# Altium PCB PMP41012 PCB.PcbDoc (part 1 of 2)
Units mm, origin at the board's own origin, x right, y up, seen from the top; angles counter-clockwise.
Board outline 69 x 32 mm, 2 copper layers (Top Layer, Bottom Layer), stack 1.575 mm thick; 63 components, 34 nets, 139 pads, 27 vias.
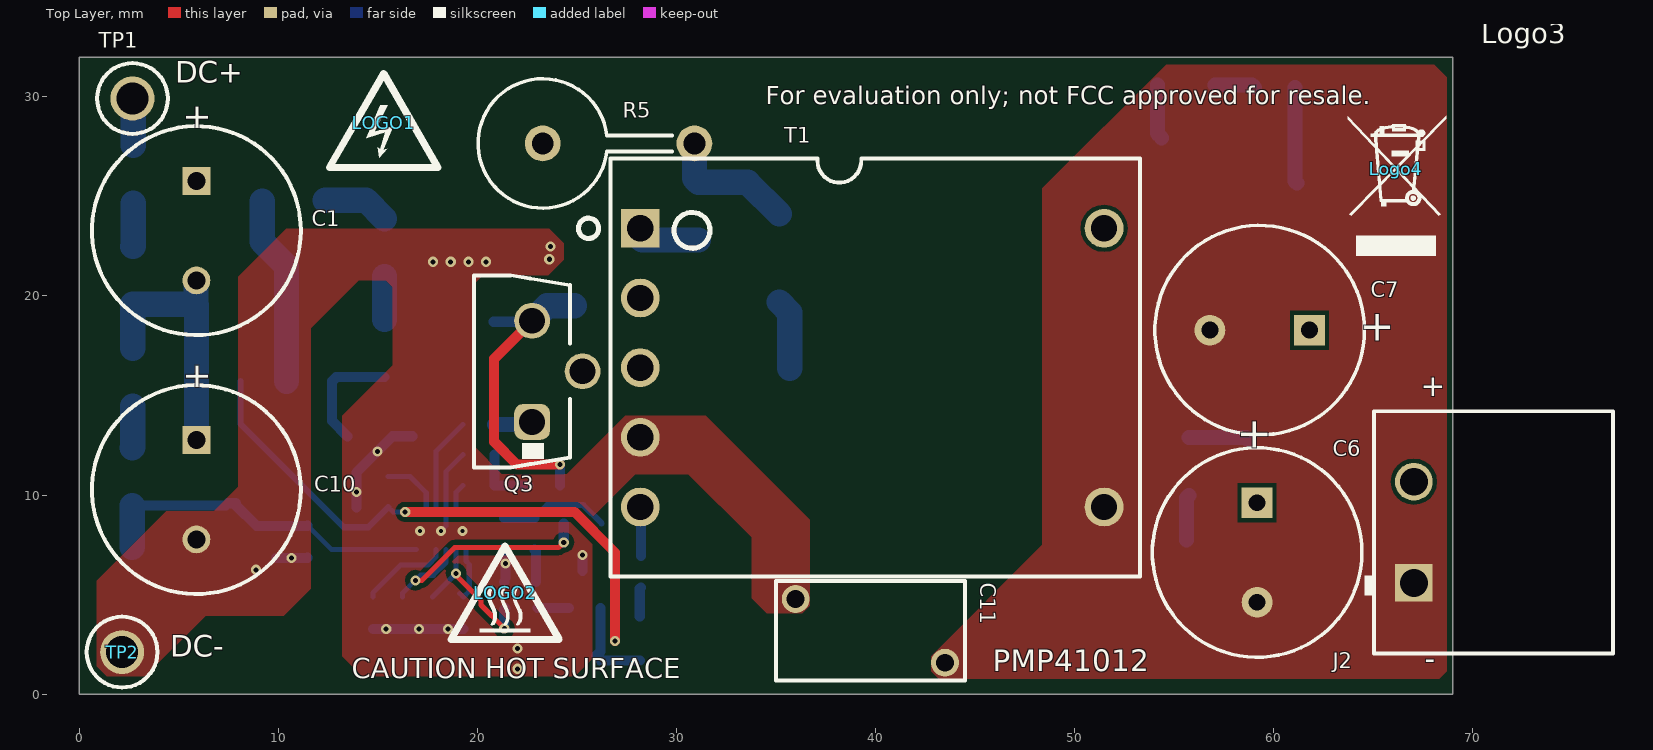
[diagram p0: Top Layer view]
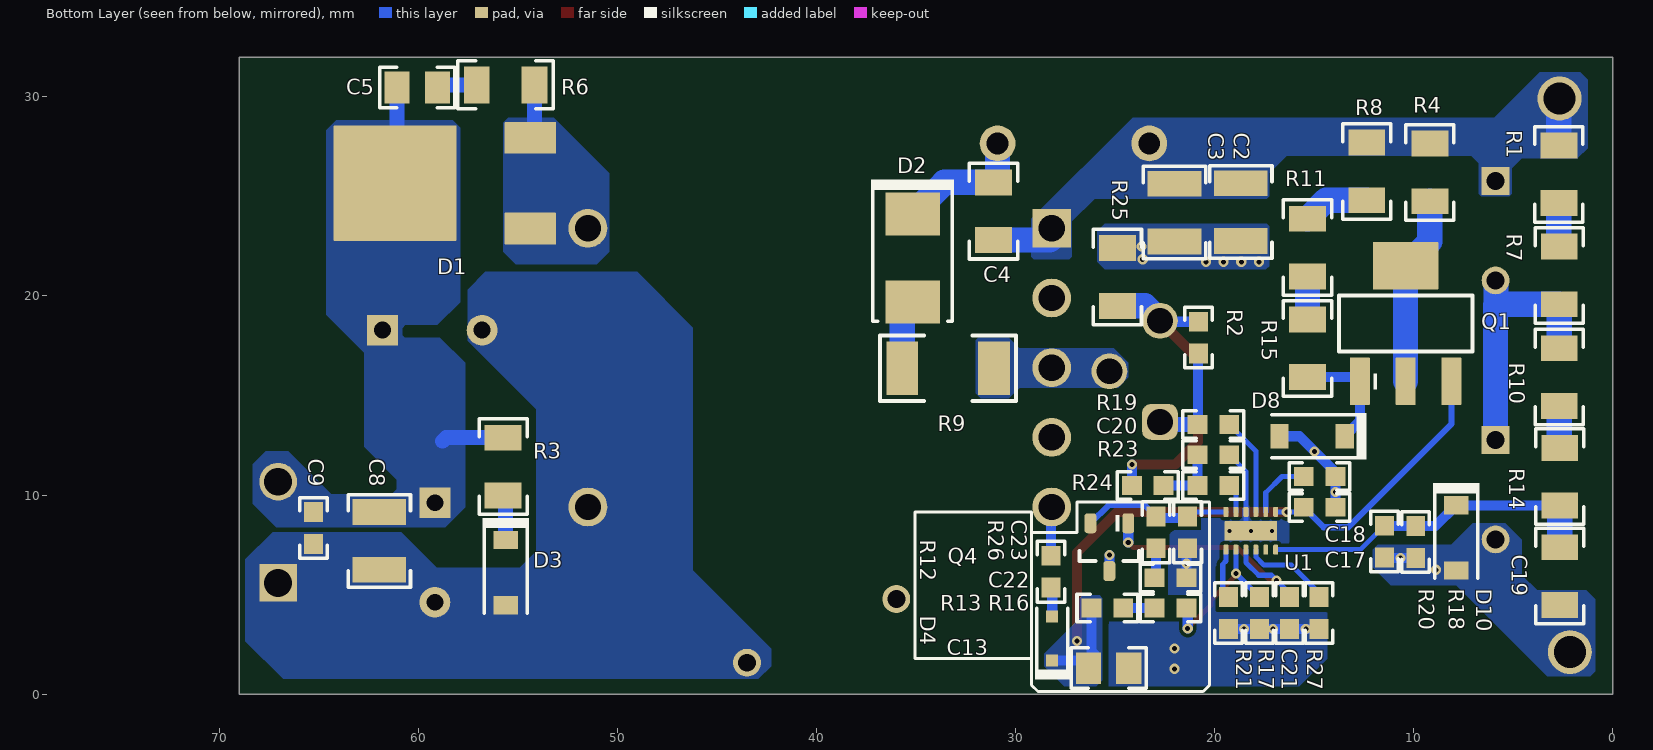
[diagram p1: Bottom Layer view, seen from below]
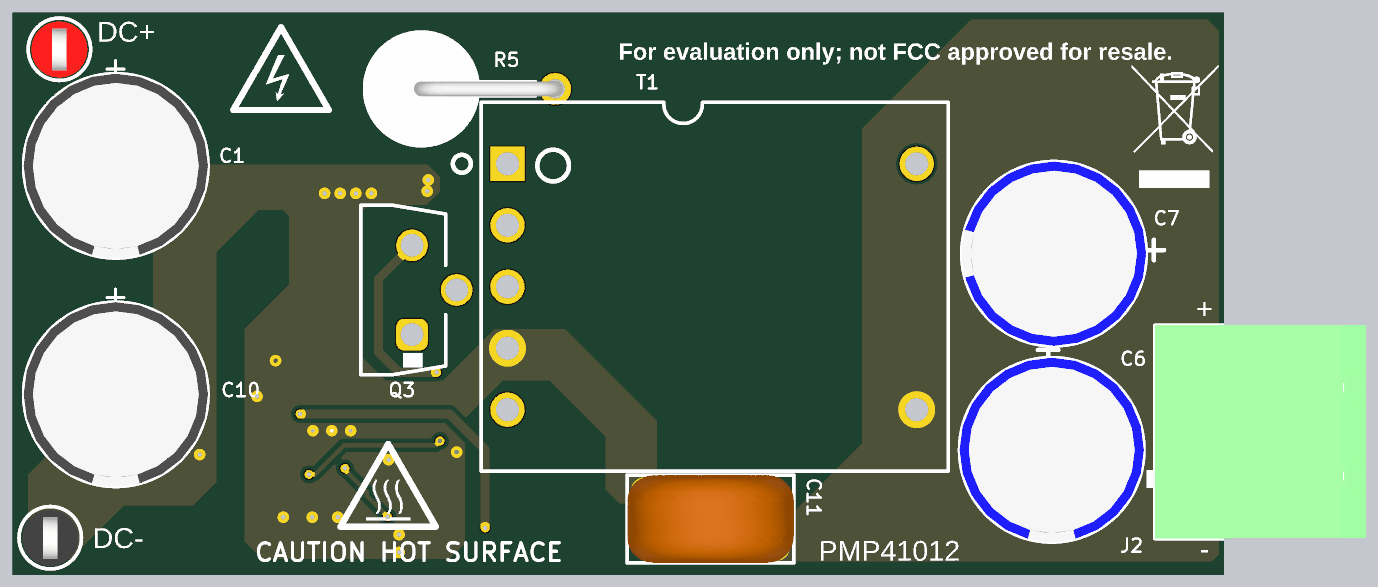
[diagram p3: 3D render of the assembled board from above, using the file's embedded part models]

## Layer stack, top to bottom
Top Solder: solder mask 0.0102, Solder Resist, Dk 3.5
Top Layer: signal copper 0.0356
Dielectric1: core 1.5037, FR-4, Dk 4.8
Bottom Layer: signal copper 0.0356
Bottom Solder: solder mask 0.0102, Solder Resist, Dk 3.5

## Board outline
0,0 69,0 69,32 0,32

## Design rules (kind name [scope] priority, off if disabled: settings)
AcuteAngle [All] p1: minimum=4.50000000000000E+0001 checktracksonly=FALSE
AssemblyTestPointUsage [All] p1: valid=2
Clearance Clearance_BoardEdge_MountingHoles [OnCopper and InComponentClass('Mounting Holes') vs IsKeepOut] p1: gap=1.016 ignorepadtopadclearanceinfootprint=FALSE except(0: Arc-Hole Track-Hole SMDPad-Hole THPad-Hole Via-Hole Fill-Hole Poly-Hole Region-Hole Text-Hole)
Clearance Clearance_BoardEdge_Poly [OnCopper and InPoly vs IsKeepOut] p2: gap=0.635 ignorepadtopadclearanceinfootprint=FALSE except(0: Arc-Hole Track-Hole SMDPad-Hole THPad-Hole Via-Hole Fill-Hole Poly-Hole Region-Hole Text-Hole)
Clearance Clearance_BoardEdge [OnCopper and Not InComponentClass('Logo') and not InComponentClass('FiducialMark') and not InRegion(1000,500,4000,800) and Not IsKeepout vs IsKeepOut] p3: gap=0.127 ignorepadtopadclearanceinfootprint=FALSE except(0: Arc-Hole Track-Hole SMDPad-Hole THPad-Hole Via-Hole Fill-Hole Poly-Hole Region-Hole Text-Hole)
Clearance Clearance_Poly [InPolygon] p4: gap=0.198 ignorepadtopadclearanceinfootprint=FALSE
Clearance [All] p5: gap=0.198 ignorepadtopadclearanceinfootprint=FALSE
ComponentClearance ComponentClearance_Logo [All] p1: gap=0.254 collisioncheckmode=3 verticalgap=0.254 showdistances=TRUE
ComponentClearance ComponentClearance_ScrewToNut [(HasFootprint('NY PMS 440 0025 PH')) vs (HasFootprint('Keystone_1902C'))] p2: gap=0.127 collisioncheckmode=3 verticalgap=0.254 showdistances=FALSE
ComponentClearance ComponentClearance_MountingHoles [InComponentClass('Mounting Holes')] p3: gap=0.254 collisioncheckmode=3 verticalgap=2540 showdistances=FALSE
ComponentClearance ComponentClearance_SmallPassives [HasFootprint('0201*') or HasFootprint('0402*') or HasFootprint('0508') or HasFootprint('0603*') or HasFootprint('0612') or HasFootprint('0805*') or HasFootprint('0815*') or HasFootprint('0830*') or HasFootprint('1206*') or HasFootprint('1210*') or HasFootprint('1808*') or HasFootprint('1812*') or HasFootprint('1825*') or HasFootprint('2010*') or HasFootprint('2220*') or HasFootprint('2225*') or HasFootprint('2512*') or HasFootprint('2728*') or HasFootprint('3518*') vs HasFootprint('0201*') or HasFootprint('0402*') or HasFootprint('0508') or HasFootprint('0603*') or HasFootprint('0612') or HasFootprint('0805*') or HasFootprint('0815*') or HasFootprint('0830*') or HasFootprint('1206*') or HasFootprint('1210*') or HasFootprint('1808*') or HasFootprint('1812*') or HasFootprint('1825*') or HasFootprint('2010*') or HasFootprint('2220*') or HasFootprint('2225*') or HasFootprint('2512*') or HasFootprint('2728*') or HasFootprint('3518*')] p4: gap=0.254 collisioncheckmode=3 verticalgap=0.254 showdistances=FALSE
ComponentClearance ComponentClearance_THtoSMT [IsThruComponent vs IsSMTComponent] p5: gap=0.254 collisioncheckmode=3 verticalgap=2540 showdistances=FALSE
ComponentClearance ComponentClearance_THtoTH [IsThruComponent vs IsThruComponent] p6: gap=0.254 collisioncheckmode=3 verticalgap=2540 showdistances=FALSE
ComponentClearance [All] p7: gap=0.254 collisioncheckmode=3 verticalgap=0.254 showdistances=FALSE
DiffPairsRouting [All] p1: maxlimit=2.54 minlimit=0.254 mostfreqgap=0.254 toplayer_minwidth=0.381 toplayer_maxwidth=0.381 toplayer_prefwidth=0.381 bottomlayer_minwidth=0.381 bottomlayer_maxwidth=0.381 bottomlayer_prefwidth=0.381 maxuncoupledlength=25.4
FabricationTestPointUsage TestPointUsage [All] p1: valid=2 allowmultiple=FALSE
FabricationTestpoint Testpoint [All] p1: side=3 testpointundercomponent=TRUE minsize=1.016 maxsize=2.54 preferedsize=1.524 minholesize=0 maxholesize=1.016 preferedholesize=0.813 testpointgrid=0.025 allowsidetop=TRUE allowsidebottom=TRUE usegrid=TRUE gridtolerance=0
FanoutControl Fanout_LCC [IsLCC] p1: bgadir=Out bgaviamode=Centered fanoutstyle=Auto fanoutdirection=Alternating viagrid=0.025 // Fanout_LCC (Default Rule)
FanoutControl Fanout_BGA [IsBGA] p2: bgadir=Out bgaviamode=Centered fanoutstyle=Auto fanoutdirection=Alternating viagrid=0.025 // Fanout_BGA (Default Rule)
FanoutControl Fanout_Default [All] p4: bgadir=Out bgaviamode=Centered fanoutstyle=Auto fanoutdirection=Alternating viagrid=0.025 // Fanout_Default (Default Rule)
FanoutControl Fanout_Small [(CompPinCount < 5)] p5: bgadir=Out bgaviamode=Centered fanoutstyle=Auto fanoutdirection=OutThenIn viagrid=0.025 // Fanout_Small (Default Rule)
HoleSize [All] p1: absolutevalues=TRUE maxlimit=6.375 minlimit=0.152 maxpercent=80.000 minpercent=20.000
MinimumAnnularRing [All] p1: minimumring=0.076
MinimumSolderMaskSliver MinimumSolderMaskSliver_Logo [InComponentClass('Logo') vs InComponentClass('Logo')] p1: minsoldermaskwidth=0.018
MinimumSolderMaskSliver [All] p2: minsoldermaskwidth=0
PlaneConnect [All] p1: planeconnectstyle=Direct reliefexpansion=0.254 reliefentries=4 reliefconductorwidth=0.254 reliefairgap=0.254
PolygonConnect [All] p1: connectstyle=Direct reliefconductorwidth=0.254 reliefentries=4 polygonreliefangle="90 Angle" airgapwidth=0.254
RoutingCorners [All] p1: cornerstyle=45-Degree minsetback=0.254 maxsetback=2.54
RoutingVias [All] p1: holewidth=0.406 width=0.864 viastyle="Through Hole" minholewidth=0.203 minwidth=0.406 maxholewidth=1.016 maxwidth=1.651
SMDToCorner [All] p1: distance=0
SilkToBoardRegionClearance [Not ((IsComment or IsDesignator) And (Hide <> 'False')) and not InRegion(1000,500,4000,800)] p1:
SilkToSilkClearance [All] p1: silktosilkclearance=0
SilkToSolderMaskClearance SilkscreenOverComponentPads [IsPad] p1: minsilkscreentomaskgap=0 clearancetoexposedcopper=TRUE
SolderMaskExpansion [All] p1: expansion=0.076
Width [All] p1: maxlimit=2.54 minlimit=0.152 preferedwidth=0.254 checkconnectedcopper=TRUE
14 further rules are at their usual default settings.

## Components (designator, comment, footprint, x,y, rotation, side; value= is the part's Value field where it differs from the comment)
C1 "B43851A9106M" B43851_1000x2000 5.893,23.281 r270 top value=10uF
C2 "GRM32DR73A223KW01L" 1210_220 18.694,24.216 r270 bottom value=0.022uF
C3 "GRM32DR73A223KW01L" 1210_220 22.021,24.191 r270 bottom value=0.022uF
C4 "C1206C562J2GACAUTO" 1206 31.115,24.257 r90 bottom value=5600pF
C5 "GRM21AR72E102KW01D" 0805_HV 60.071,30.48 r180 bottom value=1000pF
C6 "EEU-FR1E102B" FR_1000x2000 59.182,7.112 r270 top value=1000uF
C7 "EEU-FR1E102B" FR_1000x2000 59.309,18.281 r180 top value=1000uF
C8 "GRM32DR71E106KA12L" 1210_220 61.976,7.694 r270 bottom value=10uF
C9 "GRM188R71H104KA93D" 0603 65.278,8.344 r270 bottom value=0.1uF
C10 "B43851A9106M" B43851_1000x2000 5.893,10.272 r270 top value=10uF
C11 "AY2222M35Y5US63L7" AY2_950x500_Straight 39.751,3.175 r0 top value=2200pF
C13 "CGA4J3X7R1H225K125AB" 0805_HV 25.333,1.3 r180 bottom value=2.2uF
C17 "GRM188R71H104KA93D" 0603 14.732,9.385 r0 bottom value=0.1uF
C18 "GRM188R71E105KA12D" 0603 14.732,10.934 r0 bottom value=1uF
C19 "GRM319R71H334KA01D" 1206 2.667,5.929 r270 bottom value=0.33uF
C20 "GRM188R71H221KA01D" 0603 20.075,12.024 r180 bottom value=220pF
C21 "GRM188R71C474KA88D" 0603 16.256,4.076 r270 bottom value=0.47uF
C22 "GRM188R71A105KA61D" 0603 22.225,5.842 r180 bottom value=1uF
C23 "GRM188R71H102KA01D" 0603 21.361,8.128 r270 bottom value=1000pF
D1 "MBRD20150CT-13" DPAK 57.785,25.666 r0 bottom value=150V
D2 "RS1MB-13-F" SMB 35.179,21.905 r270 bottom value=1000V
D3 "MMSZ5250B-7-F" SOD-123 55.626,6.096 r270 bottom value=20V
D4 "BAV21WS-7-F" SOD-323 28.168,2.794 r90 bottom value=250V
D8 "MMSZ5245B-7-F" SOD-123 15.113,12.954 r0 bottom value=15V
D10 "MMSZ5231B-7-F" SOD-123 7.874,7.852 r270 bottom value=5.1V
J2 "1757242" PHOENIX_1757242 71.056,8.128 r90 top
LOGO1 "DANGER HIGH VOLTAGE" IEC_HighVoltage_Small 15.3,28.7 r0 top
LOGO2 "CAUTION HOT SURFACE" IEC_HotSurface_Small 21.4,5.1 r0 top
Logo3 "FCC disclaimer" FCC_disclaimer 70.923,15.736 r90 top
Logo4 "WEEE logo" WEEE_Minimum 66.159,26.4 r0 top
Q1 "IPN80R3K3P7" SOT-223 10.414,18.615 r90 bottom value=800V
Q3 "STF2N95K5" TO-220_FullPAK_Offset 22.758,16.215 r90 top value=800V
Q4 "MMBT3906" SOT-23 25.298,7.379 r270 bottom value="40 V"
R1 "CRCW1206200KJNEA" 1206 2.713,26.112 r90 bottom value=200k
R2 "RC0603FR-0747KL" 0603 20.828,17.907 r270 bottom value=47.0k
R3 "CRCW1206100RJNEA" 1206 55.753,11.43 r90 bottom value=100
R4 "CRCW120610K0FKEAHP" 1206 9.194,26.21 r90 bottom value=10.0k
R5 "PR03000202203JAC00" ERG3S_VERT 23.291,27.665 r0 top value=220k
R6 "CRCW12061R00JNEA" 1206 55.626,30.607 r0 bottom value=1.0
R7 "CRCW1206200KJNEA" 1206 2.692,21.031 r90 bottom value=200k
R8 "CRCW1206499KFKEA" 1206 12.369,26.261 r90 bottom value=499k
R9 "CRCW201020R0FKEF" 2010 33.401,16.367 r180 bottom value=20.0
R10 "CRCW1206200KJNEA" 1206 2.692,15.926 r90 bottom value=200k
R11 "CRCW1206499KFKEA" 1206 15.342,22.428 r90 bottom value=499k
R12 "CRCW060310R0JNEA" 0603 28.219,6.147 r90 bottom value=10
R13 "CRCW060349R9FKEA" 0603 25.4,4.318 r0 bottom value=49.9
R14 "CRCW1206200KJNEA" 1206 2.667,10.92 r90 bottom value=200k
R15 "CRCW1206499KFKEA" 1206 15.342,17.371 r90 bottom value=499k
R16 "CRCW06032K80FKEA" 0603 22.225,4.318 r0 bottom value=2.80k
R17 "CRCW0603200RFKEA" 0603 17.756,4.076 r90 bottom value=200
R18 "CRCW0603205KFKEA" 0603 9.906,7.645 r90 bottom value=205k
R19 "CRCW060320R0FKEA" 0603 20.075,13.548 r180 bottom value=20.0
R20 "CRCW060320K5FKEA" 0603 11.481,7.658 r90 bottom value=20.5k
R21 "CRCW06030000Z0EA" 0603 19.306,4.076 r90 bottom value=0
R23 "CRCW06030000Z0EA" 0603 20.075,10.475 r0 bottom value=0
R24 "CRCW06031K62FKEA" 0603 23.368,10.475 r180 bottom value=1.62k
R25 "CSR1206FKR100" 1206 24.892,20.955 r270 bottom value=0.1
R26 "CRCW06032K49FKEA" 0603 22.948,8.128 r90 bottom value=2.49k
R27 "CRCW0603221KFKEA" 0603 14.756,4.076 r90 bottom value=221k
T1 "070-7080" PCBComponent_1 28.194,16.398 r0 top
TP1 "5010" Keystone5010 2.681,29.921 r0 top
TP2 "5011" Keystone5011 2.159,2.108 r0 top
U1 "LM51561QDSSRQ1" DSS0012C 18.19,8.203 r270 bottom

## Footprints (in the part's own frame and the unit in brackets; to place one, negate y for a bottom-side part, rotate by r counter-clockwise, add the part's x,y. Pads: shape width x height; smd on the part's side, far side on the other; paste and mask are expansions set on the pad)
0603 [mm] "0603 from SM-752 data"
  rect 1x0.95 smd: 1(-0.8,0) 2(0.8,0)
  silkscreen extent -1.52,-0.69 1.52,0.69, body extent -0.87,-0.47 0.87,0.47, height 1
0805_HV [mil] "0805 with 30mil clearance between pads"
  rect 50x63 smd: 1(-40,0) 2(40,0)
  silkscreen extent -74,-40 74,40, body extent -43,-29 43,29, height 57
1206 [mm] "1206 from SM-752 data"
  rect 1.3x1.85 smd: 1(-1.45,0) 2(1.45,0)
  silkscreen extent -2.4,-1.21 2.4,1.21, body extent -1.7,-0.9 1.7,0.9, height 1.35
1210_220 [mm] "1210"
  rect 1.3x2.7 smd: 1(-1.45,0) 2(1.45,0)
  silkscreen extent -2.32,-1.57 2.32,1.57, body extent -1.7,-1.35 1.7,1.35, height 2.2
2010 [mm] "Chip Capacitor, Body 5.08x2.54mm, IPC Medium Density"
  rect 1.6x2.7 smd: 1(-2.3,0) 2(2.3,0)
  silkscreen extent -3.42,-1.65 3.42,1.65, body extent -2.73,-1.45 2.73,1.45, height 1.66
AY2_950x500_Straight [mm] "TH, 2-Leads, 9.5x5mm, Pin Spacing 7.5mm"
  round 1.4 hole 0.9: 1(-3.75,1.6) 2(3.75,-1.6)
  silkscreen extent -4.75,-2.5 4.75,2.5, body extent -4.74,-2.5 4.75,2.5, height 12.5
B43851_1000x2000 [mm] "TH, 2-Leads, Dia 10mm, Pin Spacing 5mm"
  rect 1.4x1.4 hole 0.9: 1(-2.5,0)
  round 1.4 hole 0.9: 2(2.5,0)
  silkscreen extent -5.25,-5.25 5.25,5.25, body extent -5.21,-5.24 5.24,5.24, height 22.01
DPAK [mm] "D-PAK, 3-Pads, Body 6.22x6.73mm (max), TO-252AA using nominal STEP model"
  rrect6% 2.6x1.6 smd: 1(-3.4,2.28) 3(-3.4,-2.28)
  rrect2% 6.2x5.8 smd paste-3: 2(3.4,0)
  body extent -3.86,-3.29 5.84,3.29, height 2.48
DSS0012C [mm] "WSON-12"
  rrect40% 0.5x0.25 smd: 1(-0.95,1.25) 2(-0.95,0.75) 3(-0.95,0.25) 4(-0.95,-0.25) 5(-0.95,-0.75) 6(-0.95,-1.25) 7(0.95,-1.25) 8(0.95,-0.75) 9(0.95,-0.25) 10(0.95,0.25) 11(0.95,0.75) 12(0.95,1.25)
  rrect11% 0.95x1.17 on Bottom Paste: 13(0,-0.685) 13(0,0.685)
  rrect11% 1x2.65 smd paste-0.5: 13(0,0)
  body extent -1,-1.5 1,1.5, height 0.81
ERG3S_VERT [mm] "PANASONIC"
  round 1.8 hole 1.1: 1(0,0) 2(7.62,0)
  silkscreen extent -3.25,-3.25 6.5,3.25, body extent -3.24,-3.25 8.04,3.22, height 20.47
FCC_disclaimer [mm]
FR_1000x2000 [mm] "PANASONIC"
  rect 1.55x1.55 hole 0.85: 1(-2.5,0)
  round 1.55 hole 0.85: 2(2.5,0)
  silkscreen extent -5.26,-5.26 5.26,5.26, body extent -5.21,-5.24 5.24,5.24, height 22.01
IEC_HighVoltage_Small [mm]
  silkscreen extent -2.72,-2.24 2.72,2.47
IEC_HotSurface_Small [mm]
  silkscreen extent -2.72,-2.36 2.72,2.35
Keystone5010 [mil] "Keystone Multipurpose loops"
  round 87 hole 63: 1(0,0)
  silkscreen extent -70,-70 70,70, body extent -63,-63 63,62, height 319
Keystone5011 [mil] "Keystone Multipurpose loops"
  round 87 hole 63: 1(0,0)
  silkscreen extent -70,-70 70,70, body extent -63,-63 63,62, height 319
PCBComponent_1 [mm] "THT, Body 22.2.0x25.0mm, 14Pins,Pitch 2.49mm"
  rect 1.95x1.95 hole 1.32: 1(0,7)
  round 1.95 hole 1.32: 2(0,3.5) 3(0,0) 4(0,-3.5) 5(0,-7) 6(23.3,-7) 7(23.3,7)
  silkscreen extent -3.11,-10.5 25.1,10.5
PHOENIX_1757242 [mm] "Header, 5.08 mm, 2x1, R/A, TH"
  rect 1.9x1.9 hole 1.4: 1(-2.54,4)
  round 1.9 hole 1.4: 2(2.54,4)
  silkscreen extent -6.08,-6 6.08,6.47, body extent -6.06,-6.02 6.1,5.98, height 8.6
SMB [mm] "Molded Diode, 2-Leads, Body 5.4x3.6mm, IPC Medium Density, based on OnSemi component dimensions"
  rect 2.159x2.743 smd: 1(-2.21,0) 2(2.21,0)
  silkscreen extent -3.94,-2.08 3.18,2.08, body extent -2.7,-1.8 2.7,1.8, height 2.32
SOD-123 [mm] "On Semi recommended land pattern"
  rect 0.915x1.22 smd: 1(-1.637,0) 2(1.637,0)
  silkscreen extent -2.74,-1.17 2.03,1.17, body extent -1.93,-0.9 1.93,0.9, height 1.35
SOD-323 [mm] "NXP recommended land pattern"
  rect 0.6x0.6 smd paste-0.05: 1(-1.1,0) 2(1.1,0)
  silkscreen extent -2.06,-0.86 1.53,0.86, body extent -1.3,-0.67 1.3,0.68, height 1.1
SOT-23 [mm] "SOT23, 3-Leads, Body 2.9x1.3mm, Pitch 0.95mm, Lead Span 2.5mm, IPC Medium Density"
  rrect50% 1x0.6 smd: 1(-1.2,0.95) 2(-1.2,-0.95) 3(1.2,0)
  silkscreen extent -1.63,-1.5 0.7,1.5, body extent -1.16,-1.45 1.21,1.45, height 1
SOT-223 [mm] "SOT223/SC73, 4-Leads, Body 6.5x3.5mm, Pitch 2.3mm, Lead Span 7mm, IPC Medium Density"
  rrect10% 2.4x1 smd: 1(-2.9,2.3) 2(-2.9,0) 3(-2.9,-2.3)
  rrect4% 2.4x3.3 smd: 4(2.9,0)
  silkscreen extent -3.32,-3.35 1.4,3.35, body extent -3.5,-3.25 3.5,3.25, height 1.62
TO-220_FullPAK_Offset [mm] "Infineon  PG-TO220-3-31"
  rrect50% 1.8x1.8 hole 1.3: 1(-2.54,0)
  round 1.8 hole 1.3: 2(0,-2.54) 3(2.54,0)
  silkscreen extent -4.82,-1.91 4.83,2.92, body extent -4.82,-2.84 4.83,2.92, height 22.91
WEEE_Minimum [mm] "WEEElie bin"
  silkscreen extent -2.42,-4.38 2.52,2.65

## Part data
C1 C10: library part CMP-0010001-3, "CAP, AL, 10 uF, 400 V, +/- 20%, 18 ohm, TH", Cap_Case=10x20mm, Manufacturer=TDK, Supplier Part Number 1=495-6020-ND, Tolerance_%=20%, Value1="18 ohm", Value2=400V, ValueDisplayed=10uF
C2 C3: library part CMP-0009197-2, "CAP, CERM, 0.022 uF, 1000 V, +/- 10%, X7R, 1210", Cap_Case=1210, Manufacturer=MuRata, Supplier Part Number 1=490-3502-1-ND, TempCo=X7R, Tolerance_%=10%, Value1=Unknown, Value2=1000V, ValueDisplayed=0.022uF
C4: library part CMP-0008627-2, "CAP, CERM, 5600 pF, 200 V, +/- 5%, C0G/NP0, AEC-Q200 Grade 1, 1206", Cap_Case=1206, Manufacturer=Kemet, Supplier Part Number 1=399-11570-1-ND, TempCo=C0G/NP0, Tolerance_%=5%, Value1=Unknown, Value2=200V, ValueDisplayed=5600pF
C5: library part CMP-0008251-2, "CAP, CERM, 1000 pF, 250 V, +/- 10%, X7R, 0805", Cap_Case=0805, Manufacturer=MuRata, Supplier Part Number 1=490-3525-1-ND, TempCo=X7R, Tolerance_%=10%, Value1=Unknown, Value2=250V, ValueDisplayed=DNP
C6 C7: "CAP, AL, 1000 µF, 25 V, +/- 20%, 0.02 ohm, TH", Cap_Case=10x20, Manufacturer=Panasonic, Supplier Part Number 1=P15349CT-ND, Tolerance_%=20, Value1="0.02 ohm", Value2=25V, ValueDisplayed=1000µF
C8: library part CMP-0009190-2, "CAP, CERM, 10 uF, 25 V, +/- 10%, X7R, 1210", Cap_Case=1210, Manufacturer=MuRata, Supplier Part Number 1=490-1867-1-ND, TempCo=X7R, Tolerance_%=10%, Value1=Unknown, Value2=25V, ValueDisplayed=10uF
C9 C17: library part CMP-0007434-4, "CAP, CERM, 0.1 uF, 50 V, +/- 10%, X7R, 0603", Cap_Case=0603, Manufacturer=MuRata, Supplier Part Number 1=490-1519-1-ND, TempCo=X7R, Tolerance_%=10%, Value1=Unknown, Value2=50V, ValueDisplayed=0.1uF
C11: "CAP, CERM, 2200 pF, X1 440 VAC/Y2 300 VAC, +/- 20%, Y5U, AEC-Q200 Grade 1, D9.5xT5mm", Cap_Case=9.5x5mm, Manufacturer=Vishay-Bccomponents, Supplier Part Number 1=BC2914-ND, TempCo=Y5U, Tolerance_%=20, ValueDisplayed=2200pF
C13: "CAP, CERM, 2.2 µF, 50 V,+/- 10%, X7R, AEC-Q200 Grade 1, 0805", Cap_Case=0805, Manufacturer=TDK, Supplier Part Number 1=445-174216-1-ND, TempCo=X7R, Tolerance_%=10, Value1="0.003288 ohm", Value2=50V, ValueDisplayed=2.2µF
C18: library part CMP-0007405-4, "CAP, CERM, 1 uF, 25 V, +/- 10%, X7R, 0603", Cap_Case=0603, Manufacturer=MuRata, Supplier Part Number 1=490-5307-1-ND, TempCo=X7R, Tolerance_%=10%, Value1=Unknown, Value2=25V, ValueDisplayed=1uF
C19: library part CMP-0008880-2, "CAP, CERM, 0.33 uF, 50 V, +/- 10%, X7R, 1206", Cap_Case=1206, Manufacturer=MuRata, Supplier Part Number 1=490-1778-1-ND, TempCo=X7R, Tolerance_%=10%, Value1=Unknown, Value2=50V, ValueDisplayed=0.33uF
C20: library part CMP-0007442-5, "CAP, CERM, 220 pF, 50 V, +/- 10%, X7R, 0603", Cap_Case=0603, Manufacturer=MuRata, Supplier Part Number 1=490-1483-1-ND, TempCo=X7R, Tolerance_%=10%, Value1=Unknown, Value2=50V, ValueDisplayed=220pF
C21: library part CMP-0007398-4, "CAP, CERM, 0.47 uF, 16 V, +/- 10%, X7R, 0603", Cap_Case=0603, Manufacturer=MuRata, Supplier Part Number 1=490-3295-1-ND, TempCo=X7R, Tolerance_%=10%, Value1=Unknown, Value2=16V, ValueDisplayed=0.47uF
C22: library part CMP-0007365-4, "CAP, CERM, 1 uF, 10 V, +/- 10%, X7R, 0603", Cap_Case=0603, Manufacturer=MuRata, Supplier Part Number 1=490-3899-1-ND, TempCo=X7R, Tolerance_%=10%, Value1="0.011 ohm", Value2=10V, ValueDisplayed=1uF
C23: library part CMP-0007432-3, "CAP, CERM, 1000 pF, 50 V, +/- 10%, X7R, 0603", Cap_Case=0603, Manufacturer=MuRata, Supplier Part Number 1=490-1494-1-ND, TempCo=X7R, Tolerance_%=10%, Value1=Unknown, Value2=50V, ValueDisplayed=1000pF
D1: library part CMP-0028958-2, "Diode, Schottky, 150 V, 10 A, DPAK", Manufacturer="Diodes Inc.", Supplier Part Number 1=MBRD20150CT-13DICT-ND, Value1=10A, Value2=0.9V
D2: library part CMP-0076889-1, "Diode, P-N, 1000 V, 1 A, SMB", Manufacturer="Diodes Inc.", Supplier Part Number 1=RS1MB-FDICT-ND, Value1=1A, Value2=1.3V
D3: library part CMP-0005756-4, "Diode, Zener, 20 V, 500 mW, SOD-123", Manufacturer="Diodes Inc.", Power_W=500mW, Value1=0.5W
D4: library part CMP-0029165-2, "Diode, Switching, 250 V, 0.25 A, AEC-Q101, SOD-323", Manufacturer="Diodes Inc.", Value1=0.25A, Value2=1.25V
D8: library part CMP-0005753-2, "Diode, Zener, 15 V, 500 mW, SOD-123", Manufacturer="Diodes Inc.", Power_W=500mW, Supplier Part Number 1=MMSZ5245B-FDICT-ND, Value1=0.5W
D10: library part CMP-0005802-1, "Diode, Zener, 5.1 V, 500 mW, SOD-123", Manufacturer="Diodes Inc.", Power_W=500mW, Supplier Part Number 1=MMSZ5231B-FDICT-ND, Value1=0.5W
J2: library part CMP-0055534-1, "Header (Shrouded), 5.08 mm, 2x1, Tin, R/A, TH", Manufacturer="Phoenix Contact", Supplier Part Number 1=277-1106-ND
LOGO1: library part CMP-0074835-1, "IEC 61010-1 High Voltage Warning"
LOGO2: library part CMP-0074837-1, "IEC 61010-1 Hot Surface Warning"
Logo3: library part CMP-0074847-1, "FCC_disclaimer"
Logo4: library part CMP-0074769-1
Q1: library part CMP-0081663-1, "MOSFET, N-CH, 800 V, SOT-223", Alternate Manufacturer=None, Manufacturer=Infineon, Value1="? ohm", Value2="? nC"
Q3: library part CMP-0001279-3, "MOSFET, N-CH, 800 V, 9 A, TO-220FP", Alternate Manufacturer=None, Manufacturer=STMicroelectronics, PartNumber=STF10N80K5, Supplier Part Number 1=497-15113-5-ND, Value2="22 nC"
Q4: library part CMP-0000325-2, "Transistor, PNP, 40 V, 0.2 A, SOT-23", Manufacturer="Fairchild Semiconductor", Supplier Part Number 1=MMBT3906FSCT-ND, Value1="0.2 A", Value2=300
R1 R7 R10 R14: library part CMP-0018624-3, "RES, 200 k, 5%, 0.25 W, AEC-Q200 Grade 0, 1206", Manufacturer=Vishay-Dale, Power_W=250mW, Supplier Part Number 1=541-200KECT-ND, TempCo="200 ppm/C", Tolerance_%=5%, Value2=0.25W, Value_Code=200k
R2: library part CMP-0023133-2, "RES, 47.0 k, 1%, 0.1 W, 0603", Manufacturer="Yageo America", Power_W=100mW, Supplier Part Number 1=311-47.0KHRCT-ND, TempCo="200 ppm/C", Tolerance_%=1%, Value2=0.1W, Value_Code=47k0, ValueDisplayed=47.0k
R3: library part CMP-0018575-3, "RES, 100, 5%, 0.25 W, AEC-Q200 Grade 0, 1206", Manufacturer=Vishay-Dale, Power_W=250mW, Supplier Part Number 1=541-100ECT-ND, TempCo="200 ppm/C", Tolerance_%=5%, Value2=0.25W, Value_Code=100R, ValueDisplayed=100
R4: library part CMP-0016578-3, "RES, 10.0 k, 1%, 0.5 W, AEC-Q200 Grade 0, 1206", Manufacturer=Vishay-Dale, Power_W=500mW, Supplier Part Number 1=541-10.0KUCT-ND, TempCo="100 ppm/C", Tolerance_%=1%, Value2=0.5W, Value_Code=10k0, ValueDisplayed=10.0k
R5: "RES, 220 k, 5%, 3 W, D5.20xL16.70mm", Manufacturer=Vishay-Bccomponents, Power_W=3, Supplier Part Number 1=PPC220KW-3JCT-ND, TempCo="250 ppm/C", Tolerance_%=5, Value1=5%, Value2=3W, Value_Code=220k
R6: library part CMP-0018617-2, "RES, 1.0, 5%, 0.25 W, 1206", Manufacturer=Vishay-Dale, Power_W=250mW, Supplier Part Number 1=541-1.0ECT-ND, TempCo="200 ppm/C", Tolerance_%=5%, Value2=0.25W, Value_Code=1R00, ValueDisplayed=DNP
R8 R11 R15: library part CMP-0017016-3, "RES, 499 k, 1%, 0.25 W, AEC-Q200 Grade 0, 1206", Manufacturer=Vishay-Dale, Power_W=250mW, Supplier Part Number 1=541-499KFCT-ND, TempCo="100 ppm/C", Tolerance_%=1%, Value2=0.25W, Value_Code=499k
R9: library part CMP-0016307-3, "RES, 20.0, 1%, 0.75 W, AEC-Q200 Grade 0, 2010", Manufacturer=Vishay-Dale, Power_W=750mW, Supplier Part Number 1=541-20.0ACCT-ND, TempCo="100 ppm/C", Tolerance_%=1%, Value2=0.75W, Value_Code=20R0, ValueDisplayed=20.0
R12: library part CMP-0025703-1, "RES, 10, 5%, 0.1 W, 0603", Manufacturer=Vishay-Dale, Power_W=100mW, Supplier Part Number 1=541-10GCT-ND, TempCo="200 ppm/C", Tolerance_%=5%, Value2=0.1W, Value_Code=10R0, ValueDisplayed=10
R13: library part CMP-0022448-4, "RES, 49.9, 1%, 0.1 W, AEC-Q200 Grade 0, 0603", Manufacturer=Vishay-Dale, Power_W=100mW, Supplier Part Number 1=541-49.9HCT-ND, TempCo="100 ppm/C", Tolerance_%=1%, Value2=0.1W, Value_Code=49R9, ValueDisplayed=49.9
R16: library part CMP-0022282-4, "RES, 2.80 k, 1%, 0.1 W, AEC-Q200 Grade 0, 0603", Manufacturer=Vishay-Dale, Power_W=100mW, Supplier Part Number 1=541-2.80KHCT-ND, TempCo="100 ppm/C", Tolerance_%=1%, Value2=0.1W, Value_Code=2k80, ValueDisplayed=2.80k
R17: library part CMP-0022201-5, "RES, 200, 1%, 0.1 W, AEC-Q200 Grade 0, 0603", Manufacturer=Vishay-Dale, Power_W=100mW, Supplier Part Number 1=541-200HCT-ND, TempCo="100 ppm/C", Tolerance_%=1%, Value2=0.1W, Value_Code=200R, ValueDisplayed=200
R18: library part CMP-0022202-4, "RES, 205 k, 1%, 0.1 W, AEC-Q200 Grade 0, 0603", Manufacturer=Vishay-Dale, Power_W=100mW, Supplier Part Number 1=541-205KHCT-ND, TempCo="100 ppm/C", Tolerance_%=1%, Value2=0.1W, Value_Code=205k
R19: library part CMP-0022206-3, "RES, 20.0, 1%, 0.1 W, 0603", Manufacturer=Vishay-Dale, Power_W=100mW, Supplier Part Number 1=541-20.0HCT-ND, TempCo="100 ppm/C", Tolerance_%=1%, Value2=0.1W, Value_Code=20R0, ValueDisplayed=20.0
R20: library part CMP-0022205-4, "RES, 20.5 k, 1%, 0.1 W, AEC-Q200 Grade 0, 0603", Manufacturer=Vishay-Dale, Power_W=100mW, Supplier Part Number 1=541-20.5KHCT-ND, TempCo="100 ppm/C", Tolerance_%=1%, Value2=0.1W, Value_Code=20k5, ValueDisplayed=20.5k
R21 R23: library part CMP-0025697-4, "RES, 0, 5%, 0.1 W, AEC-Q200 Grade 0, 0603", Manufacturer=Vishay-Dale, Power_W=100mW, Supplier Part Number 1=541-0.0GCT-ND, TempCo="200 ppm/C", Tolerance_%=5%, Value2=0.1W, Value_Code=0000, ValueDisplayed=0
R24: library part CMP-0022129-4, "RES, 1.62 k, 1%, 0.1 W, AEC-Q200 Grade 0, 0603", Manufacturer=Vishay-Dale, Power_W=100mW, Supplier Part Number 1=541-1.62KHCT-ND, TempCo="100 ppm/C", Tolerance_%=1%, Value2=0.1W, Value_Code=1k62, ValueDisplayed=1.62k
R25: "RES, 0.1, 1%, 0.5 W, 1206", Manufacturer="Stackpole Electronics Inc", Power_W=0.5, Supplier Part Number 1=CSR1206FKR100CT-ND, TempCo="100 ppm/C", Tolerance_%=1, Value1=1%, Value2=0.5W, Value_Code=R100, ValueDisplayed=0.1
R26: library part CMP-0022277-4, "RES, 2.49 k, 1%, 0.1 W, AEC-Q200 Grade 0, 0603", Manufacturer=Vishay-Dale, Power_W=100mW, Supplier Part Number 1=541-2.49KHCT-ND, TempCo="100 ppm/C", Tolerance_%=1%, Value2=0.1W, Value_Code=2k49, ValueDisplayed=2.49k
R27: library part CMP-0022216-4, "RES, 221 k, 1%, 0.1 W, AEC-Q200 Grade 0, 0603", Manufacturer=Vishay-Dale, Power_W=100mW, Supplier Part Number 1=541-221KHCT-ND, TempCo="100 ppm/C", Tolerance_%=1%, Value2=0.1W, Value_Code=221k
T1: library part "EE20/10/6 (EF20), 070-7080", "EE20/10/6 (EF20) 14-Term. EXT, THT, Horizontal", Manufacturer="Würth Elektronik Midcom", Package="EE20/10/6 (EF20)"
TP1: library part CMP-0055147-1, "Test Point, Multipurpose, Red, TH", Color=Red, Manufacturer=Keystone, Supplier Part Number 1=36-5010-ND
TP2: library part CMP-0055148-1, "Test Point, Multipurpose, Black, TH", Color=Black, Manufacturer=Keystone, Supplier Part Number 1=36-5011-ND
U1: library part CMP-0860749-1, "2.2-MHz Wide VIN 65-V Non-synchronous Boost/SEPIC/Flyback Controller with Dual Random Spread Spectrum, DSS0012C (WSON-12)", Alternate Manufacturer="Texas Instruments", Alternate PartNumber=LM51561QDSSTQ1

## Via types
v1: diameter 0.508, hole 0.254, Top Layer to Bottom Layer, 24 vias
v2: diameter 0.5, hole 0.2, Top Layer to Bottom Layer, 3 vias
